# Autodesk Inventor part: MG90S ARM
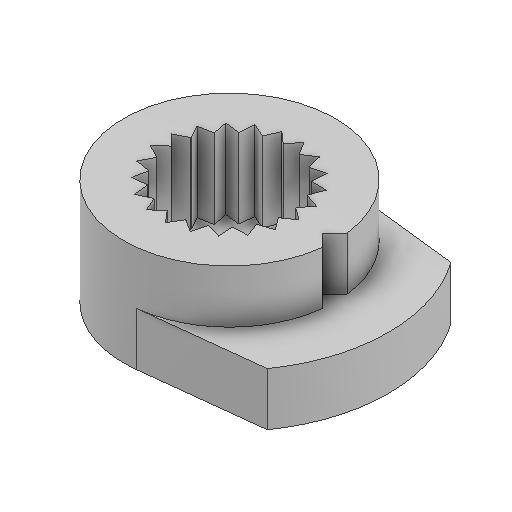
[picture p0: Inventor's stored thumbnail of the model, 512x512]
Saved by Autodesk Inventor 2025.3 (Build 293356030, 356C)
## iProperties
Created: 2024-10
Part Number: MG90S ARM
Material: Steel
Document SubType Name: Modeling
Designer: Ryzen5700u
Density: 7.85 g/cm^3
Appearance: Default
Sending System: Autodesk Translation Framework v13.20.0.188
Preprocessor: ST-DEVELOPER v20
Title: MG90S ARM.step
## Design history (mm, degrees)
feature "Body2"
sketch "Schizzo1"
  geometry: L1 (-11.15, 0)-(-10.678, 0.472) reference; L2 (-10.678, -0.472)-(-11.15, 0) reference; L3 (-14.195, -3.974)-(0.265, -2.335) reference; L4 (0.265, 2.335)-(-14.195, 3.974) reference; C1 r 1.25 at (-14.65, 0) reference; C2 r 6 at (-14.65, 0); C3 r 1 at (0, 0) reference; A1 r 4 centre (-14.65, 0) between (-10.678, 0.472) and (-14.195, 3.974) reference; A2 r 4 centre (-14.65, 0) between (-14.195, -3.974) and (-10.678, -0.472) reference; A3 r 2.35 centre (0, 0) between (0.265, -2.335) and (0.265, 2.335) reference; 3 further points
  constraints: 1 centre point, 1 coincident
  dimensions: "d0" = 12 diameter of C2
extrude "Estrusione1" cut sketch "Schizzo1" extent not by distance; stored distance "d1" = 0; taper "d2" = 0 deg
node "Solido1"
node "Linea chiusa proiettata1"
